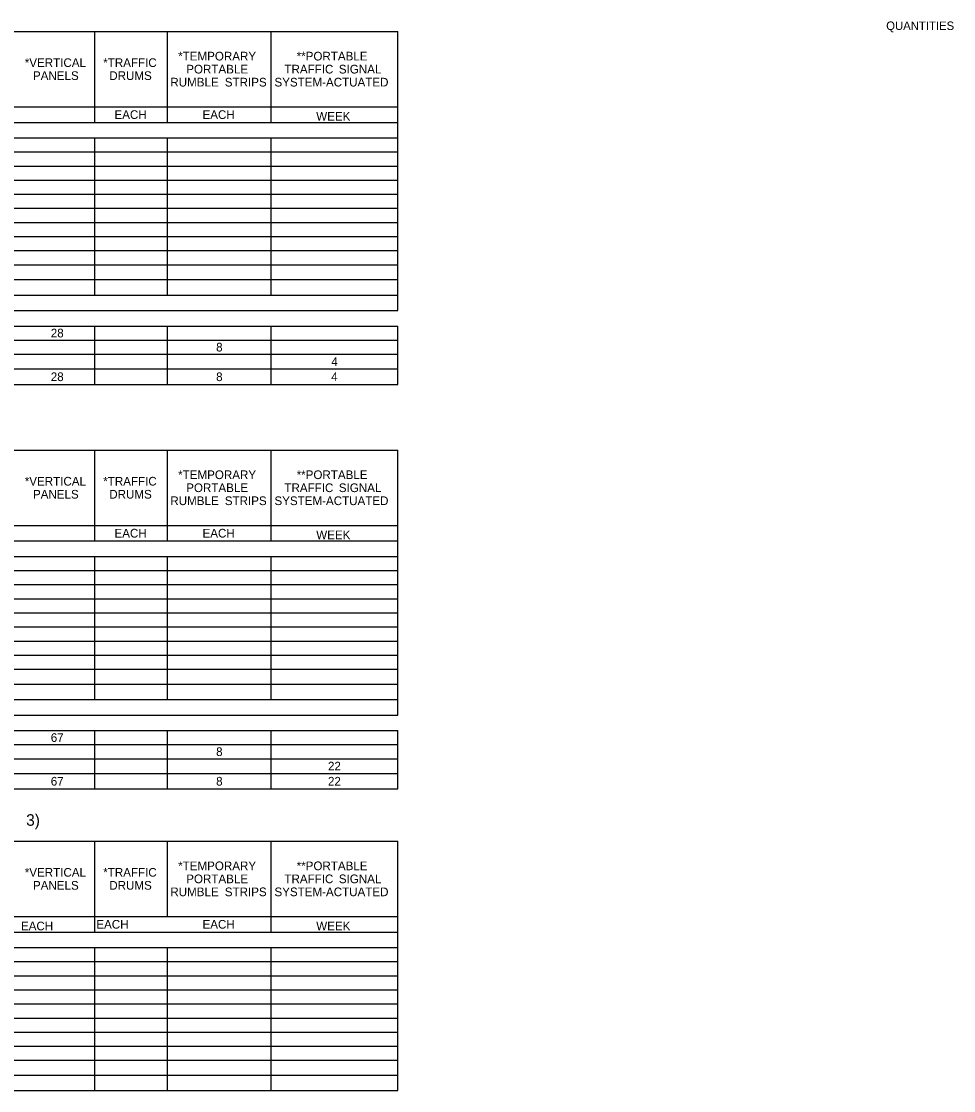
# Model space of a CAD drawing. Extents: x 542596 to 1930787, y -1948294 to 596640.
# Drawn here: x 545065 to 545710, y -1946796 to -1946056 of the extents above; entities that cross this region are included whole.
import ezdxf

# ---------------------------------------------------------------- set-up
doc = ezdxf.new("R2010")
doc.units = 0
doc.layers.add('Default', color=7, linetype='Continuous')
doc.layers.add('R_Border Prem', color=7, linetype='Continuous')

msp = doc.modelspace()

# ---------------------------------------------------------------- linework, layer by layer
at = {"layer": 'Default'}
for p, q in [((544436.43, -1946063.41), (545325.15, -1946063.41)), ((545115.52, -1946126.3), (545115.52, -1946063.41)), ((545165.73, -1946126.3), (545165.73, -1946063.41)), ((545237.4, -1946126.3), (545237.4, -1946063.41)), ((545325.15, -1946256.46), (545325.15, -1946063.41)), ((545325.15, -1946256.46), (545325.15, -1946063.41)), ((544962.93, -1946115.57), (545325.15, -1946115.57)), ((545115.52, -1946126.3), (545115.52, -1946115.57)), ((545165.73, -1946126.3), (545165.73, -1946115.57)), ((545237.4, -1946126.3), (545237.4, -1946115.57)), ((544436.43, -1946126.3), (545325.15, -1946126.3)), ((545063.36, -1946126.3), (545115.52, -1946126.3)), ((545115.52, -1946126.3), (545325.15, -1946126.3)), ((544436.43, -1946137.02), (545325.15, -1946137.02)), ((545115.52, -1946185.77), (545115.52, -1946137.02)), ((545115.52, -1946245.74), (545115.52, -1946137.02)), ((545165.73, -1946185.77), (545165.73, -1946137.02)), ((545165.73, -1946245.74), (545165.73, -1946137.02)), ((545237.4, -1946245.74), (545237.4, -1946137.02)), ((544436.43, -1946146.77), (545325.15, -1946146.77)), ((544436.43, -1946156.52), (545325.15, -1946156.52)), ((544436.43, -1946166.27), (545325.15, -1946166.27)), ((544436.43, -1946176.02), (545325.15, -1946176.02)), ((544436.43, -1946185.77), (545325.15, -1946185.77)), ((544436.43, -1946195.52), (545325.15, -1946195.52)), ((545115.52, -1946245.74), (545115.52, -1946195.52)), ((544436.43, -1946205.27), (545325.15, -1946205.27)), ((544436.43, -1946215.02), (545325.15, -1946215.02)), ((545165.73, -1946245.74), (545165.73, -1946215.02)), ((544436.43, -1946224.77), (545325.15, -1946224.77)), ((544436.43, -1946235.01), (545325.15, -1946235.01)), ((545013.15, -1946235.01), (545325.15, -1946235.01)), ((545237.4, -1946245.74), (545237.4, -1946235.01)), ((544436.43, -1946245.74), (545325.15, -1946245.74)), ((545237.4, -1946245.74), (545325.15, -1946245.74)), ((544436.43, -1946256.46), (545325.15, -1946256.46)), ((544486.65, -1946256.46), (545237.4, -1946256.46)), ((545237.4, -1946256.46), (545325.15, -1946256.46)), ((544436.43, -1946267.19), (545325.15, -1946267.19)), ((545115.52, -1946307.65), (545115.52, -1946267.19)), ((545115.52, -1946307.65), (545115.52, -1946267.19)), ((545165.73, -1946307.65), (545165.73, -1946267.19)), ((545165.73, -1946307.65), (545165.73, -1946267.19)), ((545237.4, -1946307.65), (545237.4, -1946267.19)), ((545325.15, -1946307.65), (545325.15, -1946267.19)), ((545325.15, -1946307.65), (545325.15, -1946267.19)), ((544436.43, -1946276.94), (545325.15, -1946276.94)), ((545237.4, -1946286.69), (545237.4, -1946276.94)), ((544436.43, -1946286.69), (545325.15, -1946286.69)), ((544436.43, -1946296.92), (545325.15, -1946296.92)), ((544436.43, -1946296.92), (545325.15, -1946296.92)), ((545237.4, -1946307.65), (545237.4, -1946296.92)), ((544436.43, -1946307.65), (545325.15, -1946307.65)), ((544436.43, -1946352.99), (545325.15, -1946352.99)), ((545115.52, -1946415.87), (545115.52, -1946352.99)), ((545165.73, -1946415.87), (545165.73, -1946352.99)), ((545237.4, -1946415.87), (545237.4, -1946352.99)), ((545325.15, -1946536.29), (545325.15, -1946352.99)), ((545325.15, -1946536.29), (545325.15, -1946352.99)), ((544962.93, -1946405.15), (545325.15, -1946405.15)), ((545115.52, -1946415.87), (545115.52, -1946405.15)), ((545165.73, -1946415.87), (545165.73, -1946405.15)), ((545237.4, -1946415.87), (545237.4, -1946405.15)), ((544436.43, -1946415.87), (545325.15, -1946415.87)), ((545063.36, -1946415.87), (545115.52, -1946415.87)), ((545115.52, -1946415.87), (545325.15, -1946415.87)), ((544436.43, -1946426.6), (545325.15, -1946426.6)), ((545115.52, -1946475.35), (545115.52, -1946426.6)), ((545115.52, -1946525.56), (545115.52, -1946426.6)), ((545165.73, -1946475.35), (545165.73, -1946426.6)), ((545165.73, -1946525.56), (545165.73, -1946426.6)), ((545237.4, -1946525.56), (545237.4, -1946426.6)), ((544436.43, -1946436.35), (545325.15, -1946436.35)), ((544436.43, -1946446.1), (545325.15, -1946446.1)), ((544436.43, -1946455.85), (545325.15, -1946455.85)), ((544436.43, -1946465.6), (545325.15, -1946465.6)), ((544436.43, -1946475.35), (545325.15, -1946475.35)), ((544436.43, -1946485.1), (545325.15, -1946485.1)), ((545115.52, -1946525.56), (545115.52, -1946485.1)), ((544436.43, -1946494.85), (545325.15, -1946494.85)), ((544436.43, -1946504.6), (545325.15, -1946504.6)), ((545165.73, -1946525.56), (545165.73, -1946504.6)), ((544436.43, -1946514.84), (545325.15, -1946514.84)), ((544436.43, -1946514.84), (545325.15, -1946514.84)), ((545237.4, -1946525.56), (545237.4, -1946514.84)), ((544436.43, -1946525.56), (545325.15, -1946525.56)), ((545237.4, -1946525.56), (545325.15, -1946525.56)), ((544436.43, -1946536.29), (545325.15, -1946536.29)), ((544486.65, -1946536.29), (545237.4, -1946536.29)), ((545237.4, -1946536.29), (545325.15, -1946536.29)), ((544436.43, -1946547.01), (545325.15, -1946547.01)), ((545115.52, -1946587.47), (545115.52, -1946547.01)), ((545115.52, -1946587.47), (545115.52, -1946547.01)), ((545165.73, -1946587.47), (545165.73, -1946547.01)), ((545165.73, -1946587.47), (545165.73, -1946547.01)), ((545237.4, -1946587.47), (545237.4, -1946547.01)), ((545325.15, -1946587.47), (545325.15, -1946547.01)), ((545325.15, -1946587.47), (545325.15, -1946547.01)), ((544436.43, -1946556.76), (545325.15, -1946556.76)), ((545237.4, -1946566.51), (545237.4, -1946556.76)), ((544436.43, -1946566.51), (545325.15, -1946566.51)), ((544436.43, -1946576.75), (545325.15, -1946576.75)), ((544436.43, -1946576.75), (545325.15, -1946576.75)), ((545237.4, -1946587.47), (545237.4, -1946576.75)), ((544436.43, -1946587.47), (545325.15, -1946587.47)), ((544436.43, -1946623.55), (545325.15, -1946623.55)), ((545115.52, -1946686.44), (545115.52, -1946623.55)), ((545165.73, -1946675.71), (545165.73, -1946623.55)), ((545237.4, -1946686.44), (545237.4, -1946623.55)), ((545325.15, -1946796.12), (545325.15, -1946623.55)), ((545325.15, -1946796.12), (545325.15, -1946623.55)), ((544962.93, -1946675.71), (545325.15, -1946675.71)), ((545115.52, -1946686.44), (545115.52, -1946675.71)), ((545237.4, -1946686.44), (545237.4, -1946675.71)), ((544436.43, -1946686.44), (545325.15, -1946686.44)), ((544904.92, -1946686.44), (545325.15, -1946686.44)), ((544436.43, -1946697.16), (545325.15, -1946697.16)), ((545115.52, -1946775.16), (545115.52, -1946697.16)), ((545115.52, -1946796.12), (545115.52, -1946697.16)), ((545165.73, -1946796.12), (545165.73, -1946697.16)), ((545165.73, -1946796.12), (545165.73, -1946697.16)), ((545237.4, -1946796.12), (545237.4, -1946697.16)), ((544436.43, -1946706.91), (545325.15, -1946706.91)), ((544436.43, -1946716.66), (545325.15, -1946716.66)), ((544436.43, -1946726.41), (545325.15, -1946726.41)), ((544436.43, -1946736.16), (545325.15, -1946736.16)), ((544436.43, -1946745.91), (545325.15, -1946745.91)), ((544436.43, -1946755.66), (545325.15, -1946755.66)), ((544436.43, -1946765.41), (545325.15, -1946765.41)), ((544436.43, -1946775.16), (545325.15, -1946775.16)), ((544436.43, -1946785.4), (545325.15, -1946785.4)), ((545115.52, -1946785.4), (545325.15, -1946785.4)), ((545115.52, -1946796.12), (545115.52, -1946785.4)), ((545237.4, -1946796.12), (545237.4, -1946785.4)), ((544436.43, -1946796.12), (545325.15, -1946796.12))]:
    msp.add_line(p, q, dxfattribs=at)

# ---------------------------------------------------------------- texts
for s, height, p in [('*TEMPORARY', 6, (545173.14, -1946083.49)), ('**PORTABLE', 6, (545255.16, -1946083.49)), ('*VERTICAL', 6, (545066.97, -1946087.99)), ('*TRAFFIC', 6, (545121.28, -1946087.99)), ('PORTABLE', 6, (545178.72, -1946092.49)), ('TRAFFIC', 6, (545246.68, -1946092.49)), (' SIGNAL', 6, (545282.11, -1946092.49)), ('PANELS', 6, (545072.64, -1946096.99)), ('DRUMS', 6, (545125.46, -1946096.99)), ('RUMBLE', 6, (545167.74, -1946101.49)), (' STRIPS', 6, (545203.19, -1946101.49)), ('SYSTEM-ACTUATED', 6, (545239.79, -1946101.49)), ('EACH', 6, (545129.07, -1946123.94)), ('EACH', 6, (545190.01, -1946123.94)), ('WEEK', 6, (545268.7, -1946125.1)), ('28', 6, (545084.97, -1946275.06)), ('8', 6, (545199.42, -1946284.81)), ('4', 6, (545279.15, -1946294.81)), ('28', 6, (545084.97, -1946305.29)), ('8', 6, (545199.42, -1946305.29)), ('4', 6, (545279.04, -1946305.29)), ('*TEMPORARY', 6, (545173.14, -1946373.07)), ('**PORTABLE', 6, (545255.16, -1946373.07)), ('*VERTICAL', 6, (545066.97, -1946377.57)), ('*TRAFFIC', 6, (545121.28, -1946377.57)), ('PORTABLE', 6, (545178.72, -1946382.07)), ('TRAFFIC', 6, (545246.68, -1946382.07)), (' SIGNAL', 6, (545282.11, -1946382.07)), ('PANELS', 6, (545072.64, -1946386.57)), ('DRUMS', 6, (545125.46, -1946386.57)), ('RUMBLE', 6, (545167.74, -1946391.07)), (' STRIPS', 6, (545203.19, -1946391.07)), ('SYSTEM-ACTUATED', 6, (545239.79, -1946391.07)), ('EACH', 6, (545129.07, -1946413.51)), ('EACH', 6, (545190.01, -1946413.51)), ('WEEK', 6, (545268.7, -1946414.67)), ('67', 6, (545084.97, -1946554.89)), ('8', 6, (545199.42, -1946564.64)), ('22', 6, (545276.83, -1946574.63)), ('67', 6, (545084.97, -1946585.11)), ('8', 6, (545199.42, -1946585.11)), ('22', 6, (545276.82, -1946585.11)), (' 3)', 8, (545064.95, -1946612.92)), ('*VERTICAL', 6, (545066.97, -1946648.13)), ('*TRAFFIC', 6, (545121.28, -1946648.13)), ('*TEMPORARY', 6, (545173.14, -1946643.63)), ('**PORTABLE', 6, (545255.16, -1946643.63)), ('PORTABLE', 6, (545178.72, -1946652.63)), ('TRAFFIC', 6, (545246.68, -1946652.63)), (' SIGNAL', 6, (545282.11, -1946652.63)), ('PANELS', 6, (545072.64, -1946657.13)), ('DRUMS', 6, (545125.46, -1946657.13)), ('RUMBLE', 6, (545167.74, -1946661.63)), (' STRIPS', 6, (545203.19, -1946661.63)), ('SYSTEM-ACTUATED', 6, (545239.79, -1946661.63)), ('EACH', 6, (545064.33, -1946685.24)), ('EACH', 6, (545116.5, -1946684.07)), ('EACH', 6, (545190.01, -1946684.07)), ('WEEK', 6, (545268.7, -1946685.24))]:
    msp.add_text(s, height=height, dxfattribs=at).set_placement(p)
at = {"layer": 'R_Border Prem'}
msp.add_text('QUANTITIES', height=5.862, rotation=360, dxfattribs=at).set_placement((545663.18, -1946062.39))

doc.saveas('drawing.dxf')
